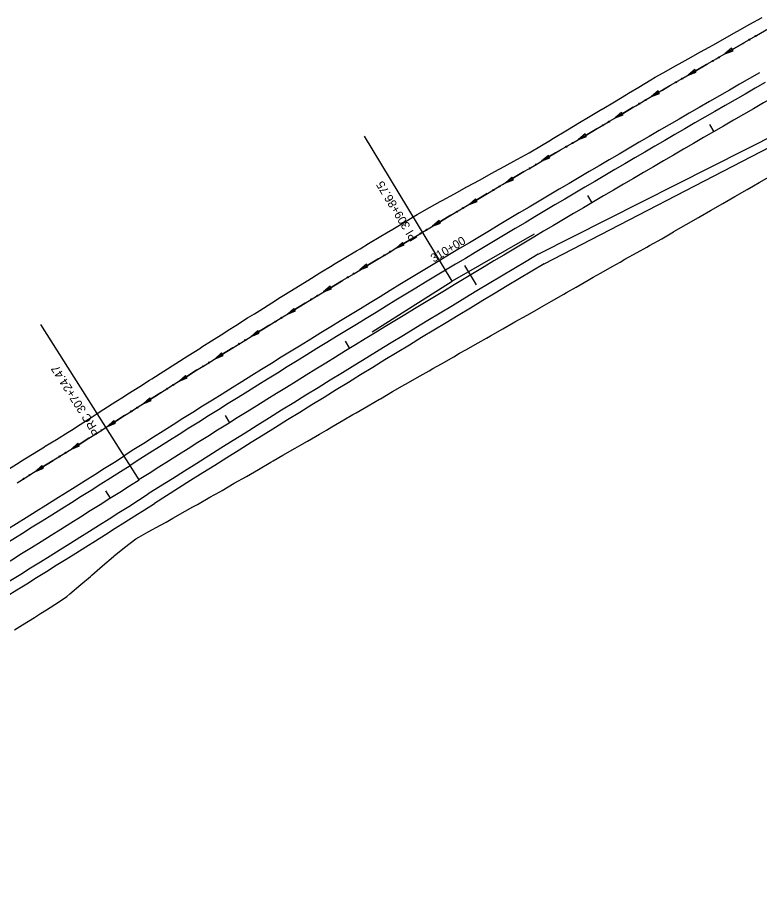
# Model space of a CAD drawing. Extents: x 1375694 to 1433473, y 1931050 to 1967991.
# Drawn here: x 1417220 to 1417746, y 1955385 to 1956000 of the extents above; entities that cross this region are included whole.
import ezdxf

# ---------------------------------------------------------------- set-up
doc = ezdxf.new("R2010")
doc.units = 0
for name, color, linetype in [('62', 7, 'Continuous'), ('R_Horz Alg', 7, 'Continuous'), ('R_Horz Alg Annot', 7, 'Continuous'), ('R_Proposed Const Limits', 7, 'Continuous'), ('R_Proposed Road', 7, 'Continuous')]:
    doc.layers.add(name, color=color, linetype=linetype)

msp = doc.modelspace()

# ---------------------------------------------------------------- linework, layer by layer
at = {"layer": '62'}
for p, q in [((1417725.94, 1955978.44), (1417721.29, 1955974.5)), ((1417721.29, 1955974.5), (1417727.01, 1955976.61)), ((1417727.01, 1955976.61), (1417725.94, 1955978.44)), ((1417699.96, 1955963.37), (1417695.3, 1955959.45)), ((1417695.3, 1955959.45), (1417701.02, 1955961.54)), ((1417701.02, 1955961.54), (1417699.96, 1955963.37)), ((1417673.98, 1955948.28), (1417669.35, 1955944.32)), ((1417669.35, 1955944.32), (1417675.05, 1955946.45)), ((1417675.05, 1955946.45), (1417673.98, 1955948.28)), ((1417648.1, 1955933.02), (1417643.48, 1955929.05)), ((1417643.48, 1955929.05), (1417649.18, 1955931.19)), ((1417649.18, 1955931.19), (1417648.1, 1955933.02)), ((1417622.24, 1955917.76), (1417617.59, 1955913.82)), ((1417617.59, 1955913.82), (1417623.3, 1955915.93)), ((1417623.3, 1955915.93), (1417622.24, 1955917.76)), ((1417596.3, 1955902.6), (1417591.67, 1955898.63)), ((1417591.67, 1955898.63), (1417597.38, 1955900.78)), ((1417597.38, 1955900.78), (1417596.3, 1955902.6)), ((1417570.5, 1955887.21), (1417565.9, 1955883.21)), ((1417565.9, 1955883.21), (1417571.59, 1955885.39)), ((1417571.59, 1955885.39), (1417570.5, 1955887.21)), ((1417544.71, 1955871.81), (1417540.09, 1955867.84)), ((1417540.09, 1955867.84), (1417545.79, 1955869.99)), ((1417545.79, 1955869.99), (1417544.71, 1955871.81)), ((1417518.88, 1955856.46), (1417514.28, 1955852.48)), ((1417514.28, 1955852.48), (1417519.97, 1955854.65)), ((1417519.97, 1955854.65), (1417518.88, 1955856.46)), ((1417493.11, 1955841.02), (1417488.52, 1955837.02)), ((1417488.52, 1955837.02), (1417494.21, 1955839.21)), ((1417494.21, 1955839.21), (1417493.11, 1955841.02)), ((1417467.39, 1955825.5), (1417462.81, 1955821.49)), ((1417462.81, 1955821.49), (1417468.49, 1955823.69)), ((1417468.49, 1955823.69), (1417467.39, 1955825.5)), ((1417441.69, 1955809.95), (1417437.12, 1955805.93)), ((1417437.12, 1955805.93), (1417442.79, 1955808.14)), ((1417442.79, 1955808.14), (1417441.69, 1955809.95)), ((1417416.05, 1955794.29), (1417411.5, 1955790.25)), ((1417411.5, 1955790.25), (1417417.16, 1955792.49)), ((1417417.16, 1955792.49), (1417416.05, 1955794.29)), ((1417390.48, 1955778.53), (1417385.93, 1955774.47)), ((1417385.93, 1955774.47), (1417391.59, 1955776.73)), ((1417391.59, 1955776.73), (1417390.48, 1955778.53)), ((1417364.93, 1955762.73), (1417360.39, 1955758.66)), ((1417366.05, 1955760.93), (1417364.93, 1955762.73)), ((1417360.39, 1955758.66), (1417366.05, 1955760.93)), ((1417339.43, 1955746.84), (1417334.91, 1955742.76)), ((1417334.91, 1955742.76), (1417340.56, 1955745.05)), ((1417340.56, 1955745.05), (1417339.43, 1955746.84)), ((1417313.99, 1955730.86), (1417309.48, 1955726.77)), ((1417315.12, 1955729.07), (1417313.99, 1955730.86)), ((1417309.48, 1955726.77), (1417315.12, 1955729.07)), ((1417288.6, 1955714.81), (1417284.1, 1955710.71)), ((1417284.1, 1955710.71), (1417289.73, 1955713.03)), ((1417289.73, 1955713.03), (1417288.6, 1955714.81)), ((1417263.22, 1955698.77), (1417258.68, 1955694.71)), ((1417258.68, 1955694.71), (1417264.34, 1955696.97)), ((1417264.34, 1955696.97), (1417263.22, 1955698.77)), ((1417237.67, 1955682.98), (1417233.12, 1955678.93)), ((1417238.78, 1955681.17), (1417237.67, 1955682.98)), ((1417233.12, 1955678.93), (1417238.78, 1955681.17))]:
    msp.add_line(p, q, dxfattribs=at)
for points in [[(1417220.12, 1955670.89), (1417227.66, 1955675.58), (1417228.58, 1955676.14), (1417237.07, 1955681.36), (1417245.55, 1955686.59), (1417246.2, 1955686.99), (1417254.02, 1955691.83), (1417262.49, 1955697.07), (1417264.71, 1955698.44), (1417270.95, 1955702.34), (1417279.35, 1955707.69), (1417283.11, 1955710.08), (1417287.8, 1955713.05), (1417296.28, 1955718.42), (1417301.64, 1955721.82), (1417304.76, 1955723.79), (1417313.25, 1955729.14), (1417320.2, 1955733.52), (1417321.75, 1955734.49), (1417330.25, 1955739.83), (1417338.75, 1955745.17), (1417338.78, 1955745.18), (1417347.26, 1955750.49), (1417355.78, 1955755.8), (1417357.39, 1955756.79), (1417364.31, 1955761.09), (1417372.84, 1955766.38), (1417376.03, 1955768.35), (1417381.38, 1955771.66), (1417389.92, 1955776.94), (1417394.69, 1955779.89), (1417398.46, 1955782.21), (1417407, 1955787.48), (1417413.36, 1955791.4), (1417415.55, 1955792.74), (1417424.11, 1955798), (1417432.07, 1955802.86), (1417432.67, 1955803.23), (1417441.25, 1955808.44), (1417449.84, 1955813.65), (1417450.82, 1955814.24), (1417458.42, 1955818.84), (1417467.01, 1955824.04), (1417469.59, 1955825.6), (1417475.6, 1955829.23), (1417484.2, 1955834.42), (1417488.37, 1955836.93), (1417492.8, 1955839.6), (1417501.4, 1955844.76), (1417507.17, 1955848.22), (1417510.01, 1955849.92), (1417518.63, 1955855.08), (1417526, 1955859.48), (1417527.25, 1955860.22), (1417535.88, 1955865.34), (1417544.51, 1955870.46), (1417544.87, 1955870.67), (1417553.14, 1955875.59), (1417561.77, 1955880.73), (1417563.71, 1955881.9), (1417570.37, 1955885.9), (1417578.98, 1955891.06), (1417582.52, 1955893.18), (1417587.59, 1955896.21), (1417596.23, 1955901.33), (1417601.4, 1955904.36), (1417604.89, 1955906.4), (1417613.56, 1955911.47), (1417620.34, 1955915.43), (1417622.23, 1955916.53), (1417630.9, 1955921.58), (1417639.25, 1955926.54), (1417639.53, 1955926.71), (1417648.17, 1955931.82), (1417656.81, 1955936.93), (1417658.13, 1955937.71), (1417665.46, 1955942.03), (1417674.11, 1955947.12), (1417677.04, 1955948.83), (1417682.78, 1955952.18), (1417691.46, 1955957.22), (1417696, 1955959.86), (1417700.14, 1955962.26), (1417708.83, 1955967.28), (1417714.99, 1955970.84), (1417717.52, 1955972.31), (1417726.2, 1955977.36), (1417733.95, 1955981.87), (1417734.87, 1955982.4), (1417743.54, 1955987.39), (1417752.21, 1955992.38)], [(1417734.25, 1955982.05), (1417733.95, 1955981.87), (1417726.2, 1955977.36), (1417721.29, 1955974.5)], [(1417734.29, 1955982.07), (1417734.25, 1955982.05)], [(1417708.28, 1955966.96), (1417700.14, 1955962.26), (1417696, 1955959.86), (1417695.3, 1955959.45)], [(1417708.31, 1955966.98), (1417708.28, 1955966.96)], [(1417682.29, 1955951.89), (1417677.04, 1955948.83), (1417674.11, 1955947.12), (1417669.35, 1955944.32)], [(1417682.33, 1955951.91), (1417682.29, 1955951.89)], [(1417656.39, 1955936.68), (1417648.17, 1955931.82), (1417643.48, 1955929.05)], [(1417656.42, 1955936.7), (1417656.39, 1955936.68)], [(1417630.55, 1955921.38), (1417622.23, 1955916.53), (1417620.34, 1955915.43), (1417617.59, 1955913.82)], [(1417630.58, 1955921.39), (1417630.55, 1955921.38)], [(1417604.6, 1955906.24), (1417601.4, 1955904.36), (1417596.23, 1955901.33), (1417591.67, 1955898.63)], [(1417604.64, 1955906.25), (1417604.6, 1955906.24)], [(1417578.76, 1955890.93), (1417570.37, 1955885.9), (1417565.9, 1955883.21)], [(1417578.79, 1955890.95), (1417578.76, 1955890.93)], [(1417552.99, 1955875.5), (1417544.87, 1955870.67), (1417544.51, 1955870.46), (1417540.09, 1955867.84)], [(1417553.02, 1955875.52), (1417552.99, 1955875.5)], [(1417527.16, 1955860.16), (1417526, 1955859.48), (1417518.63, 1955855.08), (1417514.28, 1955852.48)], [(1417527.19, 1955860.18), (1417527.16, 1955860.16)], [(1417501.38, 1955844.75), (1417492.8, 1955839.6), (1417488.52, 1955837.02)], [(1417501.41, 1955844.77), (1417501.4, 1955844.76), (1417501.38, 1955844.75)], [(1417475.64, 1955829.26), (1417475.6, 1955829.23), (1417469.59, 1955825.6), (1417467.01, 1955824.04), (1417462.81, 1955821.49)], [(1417475.67, 1955829.28), (1417475.64, 1955829.26)], [(1417449.94, 1955813.71), (1417449.84, 1955813.65), (1417441.25, 1955808.44), (1417437.12, 1955805.93)], [(1417449.97, 1955813.73), (1417449.94, 1955813.71)], [(1417424.28, 1955798.1), (1417424.11, 1955798), (1417415.55, 1955792.74), (1417413.36, 1955791.4), (1417411.5, 1955790.25)], [(1417424.31, 1955798.12), (1417424.28, 1955798.1)], [(1417398.69, 1955782.36), (1417398.46, 1955782.21), (1417394.69, 1955779.89), (1417389.92, 1955776.94), (1417385.93, 1955774.47)], [(1417398.73, 1955782.38), (1417398.69, 1955782.36)], [(1417373.14, 1955766.57), (1417372.84, 1955766.38), (1417364.31, 1955761.09), (1417360.39, 1955758.66)], [(1417373.17, 1955766.59), (1417373.14, 1955766.57)], [(1417347.63, 1955750.72), (1417347.26, 1955750.49), (1417338.78, 1955745.18), (1417338.75, 1955745.17), (1417334.91, 1955742.76)], [(1417347.66, 1955750.74), (1417347.63, 1955750.72)], [(1417322.18, 1955734.76), (1417321.75, 1955734.49), (1417320.2, 1955733.52), (1417313.25, 1955729.14), (1417309.48, 1955726.77)], [(1417322.21, 1955734.78), (1417322.18, 1955734.76)], [(1417296.77, 1955718.74), (1417296.28, 1955718.42), (1417287.8, 1955713.05), (1417284.1, 1955710.71)], [(1417296.8, 1955718.76), (1417296.77, 1955718.74)], [(1417271.41, 1955702.64), (1417270.95, 1955702.34), (1417264.71, 1955698.44), (1417262.49, 1955697.07), (1417258.68, 1955694.71)], [(1417271.44, 1955702.66), (1417271.41, 1955702.64)], [(1417245.89, 1955686.8), (1417245.55, 1955686.59), (1417237.07, 1955681.36), (1417233.12, 1955678.93)], [(1417245.92, 1955686.82), (1417245.89, 1955686.8)], [(1417220.36, 1955671.04), (1417220.33, 1955671.02)]]:
    msp.add_lwpolyline(points, dxfattribs=at)
for centre in [(1417738.63, 1955984.52), (1417742.97, 1955987.02), (1417716.98, 1955971.95), (1417712.65, 1955969.44), (1417686.65, 1955954.39), (1417690.99, 1955956.9), (1417665.05, 1955941.75), (1417660.73, 1955939.21), (1417634.88, 1955923.91), (1417639.19, 1955926.46), (1417608.96, 1955908.74), (1417613.28, 1955911.27), (1417583.09, 1955893.48), (1417587.39, 1955896.05), (1417557.32, 1955878.04), (1417561.62, 1955880.6), (1417531.49, 1955862.7), (1417535.8, 1955865.26), (1417505.7, 1955847.3), (1417510, 1955849.88), (1417479.96, 1955831.82), (1417484.25, 1955834.41), (1417454.25, 1955816.28), (1417458.54, 1955818.87), (1417428.58, 1955800.69), (1417432.86, 1955803.3), (1417407.25, 1955787.59), (1417402.99, 1955784.96), (1417377.43, 1955769.18), (1417381.69, 1955771.81), (1417356.16, 1955755.99), (1417351.91, 1955753.34), (1417326.45, 1955737.4), (1417330.69, 1955740.07), (1417305.27, 1955724.06), (1417301.03, 1955721.39), (1417279.9, 1955707.99), (1417275.67, 1955705.3), (1417250.18, 1955689.41), (1417254.44, 1955692.04), (1417228.87, 1955676.28), (1417224.61, 1955673.64)]:
    msp.add_circle(centre, 0.375, dxfattribs=at)
at = {"layer": 'R_Horz Alg'}
for centre, start, end in [((1423444.94, 1945996.61), 119.767055, 122.3894), ((1411168.28, 1965349.45), 299.767055, 302.3894)]:
    msp.add_arc(centre, 11459.16, start, end, dxfattribs=at)
at = {"layer": 'R_Horz Alg Annot'}
for p in [(1417586.15, 1955846.74), (1417471.46, 1955777.61)]:
    msp.add_line(p, (1417528.09, 1955813.53), dxfattribs=at)
for points in [[(1417710.33, 1955924.55), (1417713.33, 1955919.36)], [(1417528.09, 1955813.53), (1417466.14, 1955916.3)], [(1417623.91, 1955874.13), (1417626.96, 1955868.96)], [(1417536.91, 1955824.67), (1417545.15, 1955810.96)], [(1417306.61, 1955673.03), (1417236.97, 1955782.81)], [(1417452.41, 1955771.04), (1417455.55, 1955765.92)], [(1417367.34, 1955718.37), (1417370.52, 1955713.28)], [(1417282.73, 1955665.02), (1417285.93, 1955659.95)]]:
    msp.add_lwpolyline(points, dxfattribs=at)
at = {"layer": 'R_Proposed Const Limits'}
for points in [[(1417214.06, 1955680.58), (1417221.6, 1955685.26), (1417222.52, 1955685.82), (1417231, 1955691.03), (1417239.47, 1955696.26), (1417240.12, 1955696.65), (1417247.94, 1955701.48), (1417256.4, 1955706.73), (1417258.61, 1955708.1), (1417264.83, 1955712.02), (1417273.19, 1955717.41), (1417276.93, 1955719.83), (1417281.6, 1955722.83), (1417290.06, 1955728.26), (1417295.41, 1955731.69), (1417298.52, 1955733.68), (1417306.99, 1955739.09), (1417313.91, 1955743.51), (1417315.46, 1955744.49), (1417323.94, 1955749.88), (1417332.43, 1955755.26), (1417332.45, 1955755.28), (1417340.92, 1955760.63), (1417349.42, 1955766), (1417351.02, 1955767.01), (1417357.88, 1955771.41), (1417366.38, 1955776.77), (1417369.54, 1955778.8), (1417374.88, 1955782.14), (1417383.37, 1955787.52), (1417388.11, 1955790.53), (1417391.87, 1955792.87), (1417400.38, 1955798.22), (1417406.73, 1955802.16), (1417408.91, 1955803.53), (1417417.44, 1955808.84), (1417425.38, 1955813.76), (1417425.99, 1955814.13), (1417434.55, 1955819.4), (1417443.12, 1955824.64), (1417444.1, 1955825.24), (1417451.75, 1955829.8), (1417460.36, 1955834.98), (1417462.96, 1955836.51), (1417468.98, 1955840.14), (1417477.61, 1955845.3), (1417481.78, 1955847.81), (1417486.22, 1955850.47), (1417494.85, 1955855.62), (1417500.64, 1955859.07), (1417503.48, 1955860.77), (1417512.19, 1955865.79), (1417519.73, 1955869.93), (1417521, 1955870.63), (1417529.81, 1955875.48), (1417538.64, 1955880.3), (1417539, 1955880.49), (1417547.45, 1955885.13), (1417556.27, 1955889.96), (1417558.26, 1955891.06), (1417565.07, 1955894.82), (1417573.88, 1955899.67), (1417577.51, 1955901.65), (1417582.7, 1955904.49), (1417591.36, 1955909.58), (1417596.5, 1955912.67), (1417599.97, 1955914.76), (1417608.59, 1955919.91), (1417615.33, 1955923.95), (1417617.21, 1955925.07), (1417625.83, 1955930.23), (1417634.16, 1955935.25), (1417634.44, 1955935.42), (1417643.04, 1955940.61), (1417651.66, 1955945.78), (1417652.97, 1955946.57), (1417660.27, 1955950.96), (1417668.88, 1955956.13), (1417671.82, 1955957.84), (1417677.62, 1955961.1), (1417686.38, 1955966.01), (1417690.97, 1955968.58), (1417695.15, 1955970.92), (1417703.92, 1955975.82), (1417710.14, 1955979.29), (1417712.69, 1955980.72), (1417721.45, 1955985.64), (1417729.29, 1955990.03), (1417730.21, 1955990.55), (1417738.95, 1955995.42), (1417747.69, 1956000.27)], [(1417304.14, 1955631.1), (1417306.43, 1955632.39), (1417312.89, 1955636.05), (1417321.69, 1955640.89), (1417325.63, 1955643.05), (1417330.39, 1955645.83), (1417339.12, 1955650.68), (1417344.65, 1955653.72), (1417347.84, 1955655.55), (1417356.47, 1955660.55), (1417363.61, 1955664.5), (1417365.2, 1955665.38), (1417373.76, 1955670.51), (1417382.47, 1955675.37), (1417382.5, 1955675.38), (1417391.13, 1955680.33), (1417399.75, 1955685.33), (1417401.37, 1955686.27), (1417408.38, 1955690.32), (1417417.01, 1955695.32), (1417420.23, 1955697.18), (1417425.64, 1955700.32), (1417434.26, 1955705.31), (1417439.08, 1955708.11), (1417442.88, 1955710.32), (1417451.5, 1955715.33), (1417457.91, 1955719.06), (1417460.12, 1955720.34), (1417468.73, 1955725.35), (1417476.75, 1955729.99), (1417477.36, 1955730.35), (1417485.99, 1955735.33), (1417494.63, 1955740.3), (1417495.62, 1955740.87), (1417503.29, 1955745.24), (1417511.94, 1955750.18), (1417514.53, 1955751.66), (1417520.59, 1955755.12), (1417529.24, 1955760.08), (1417533.44, 1955762.48), (1417537.9, 1955765.01), (1417546.54, 1955769.97), (1417552.35, 1955773.27), (1417555.21, 1955774.88), (1417563.91, 1955779.75), (1417571.31, 1955783.99), (1417572.56, 1955784.7), (1417581.26, 1955789.55), (1417589.91, 1955794.49), (1417590.27, 1955794.7), (1417598.56, 1955799.43), (1417607.23, 1955804.34), (1417609.18, 1955805.47), (1417615.86, 1955809.33), (1417624.53, 1955814.23), (1417628.08, 1955816.28), (1417633.15, 1955819.21), (1417641.8, 1955824.15), (1417646.99, 1955827.05), (1417650.5, 1955829.02), (1417659.19, 1955833.88), (1417665.99, 1955837.69), (1417667.88, 1955838.75), (1417676.57, 1955843.62), (1417684.92, 1955848.43), (1417685.2, 1955848.59), (1417693.83, 1955853.56), (1417702.46, 1955858.53), (1417703.78, 1955859.29), (1417711.09, 1955863.5), (1417719.73, 1955868.46), (1417722.65, 1955870.13), (1417728.38, 1955873.4), (1417737.02, 1955878.35), (1417741.5, 1955881), (1417745.59, 1955883.42), (1417754.21, 1955888.4)], [(1417218.2, 1955566.71), (1417223.86, 1955570.25), (1417232.38, 1955575.55), (1417236.8, 1955578.34), (1417240.87, 1955580.91), (1417249.35, 1955586.28), (1417255.24, 1955590.22), (1417257.49, 1955592.19), (1417265.22, 1955598.77), (1417272.13, 1955604.57), (1417272.95, 1955605.32), (1417280.62, 1955611.99), (1417288.3, 1955618.61), (1417288.9, 1955619.1), (1417296.12, 1955625.02), (1417304.14, 1955631.1)]]:
    msp.add_lwpolyline(points, dxfattribs=at)
at = {"layer": 'R_Proposed Road'}
for p, q in [((1417589.16, 1955832.63), (1417767.67, 1955922.91)), ((1417593.26, 1955825.75), (1417770.65, 1955917.7))]:
    msp.add_line(p, q, dxfattribs=at)
for centre, radius, start, end in [((1423444.94, 1945996.61), 11479.16, 119.767055, 122.3894), ((1423444.94, 1945996.61), 11471.16, 119.767055, 122.3894), ((1423444.94, 1945996.61), 11447.16, 120.767055, 122.3894), ((1423444.94, 1945996.61), 11439.16, 120.767055, 122.3894), ((1411168.28, 1965349.45), 11439.16, 299.767055, 302.3894), ((1411168.28, 1965349.45), 11447.16, 299.767055, 302.3894), ((1411168.28, 1965349.45), 11471.16, 299.767055, 302.3894), ((1411168.28, 1965349.45), 11479.16, 299.767055, 302.3894)]:
    msp.add_arc(centre, radius, start, end, dxfattribs=at)

# ---------------------------------------------------------------- texts
at = {"layer": 'R_Horz Alg'}
msp.add_text('+', height=1, rotation=32.3894, dxfattribs=at).set_placement((1417306.52, 1955672.38))
at = {"layer": 'R_Horz Alg Annot'}
for s, rotation, p in [('PI 309+86.75', 121.07823, (1417503.86, 1955844.03)), ('310+00', 31.01175, (1417515.17, 1955826.62)), ('PRC 307+24.47', 122.3894, (1417279.57, 1955706.33))]:
    msp.add_text(s, height=6, rotation=rotation, dxfattribs=at).set_placement(p)

doc.saveas('drawing.dxf')
